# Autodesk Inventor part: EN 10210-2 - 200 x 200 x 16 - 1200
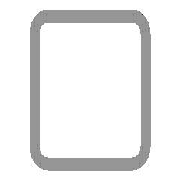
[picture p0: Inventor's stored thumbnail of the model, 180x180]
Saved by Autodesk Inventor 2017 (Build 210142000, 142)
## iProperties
IsCustomPart: 1
Created: 2016-02
Part Number: EN 10210-2 - 200 x 200 x 16 - 1200
Material: Steel, Mild
Description: Tube
Document SubType Name: Modeling
Standard: DIN
Designer: iusti
Standard Revision: 2006-07
Standards Organization: DIN
Language: en-US
Size Designation: 200 x 200 x 16
Categories: <MemberInstance><Categories><Category DisplayName="Structural Shapes" InternalName="089c4875-fa83-4c05-b084-43b9cc11f5ed" Mnemonic="GRDR"><CategoryParameter Dis
Stock Number: 200 x 200 x 16
Density: 7.85 g/cm^3
Appearance: Semi-Polished
Mass: 90285.3 g
Surface Area: 14358.6 cm^2
Volume: 11501.3 cm^3
_CCFamilyMember: 94
_CCFamilyDisplayName: DIN EN 10210-2 (Square) - Tube — Sizes in parentheses have been withdrawn
_FrameMemberDoc: Frame Member File
_Version: 15.0.0
_GetPNFromCC: 1
G_L: 1200.000 mm
G_W: 200.000 mm
G_H: 200.000 mm
+D0655DDE-97F9-4B99-A490-E36C02108510+CUTDETAIL1: Miter 45.00 deg
+B95BDB02-C4C2-4ECB-9363-19BA39C44CCB+CUTDETAIL2: Miter 45.00 deg
Author: iusti
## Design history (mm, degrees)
node "Start plane"
node "End plane"
sketch "Sketch"
  geometry: L1 (-100, -76)-(-100, 76); L2 (-76, 100)-(76, 100); L3 (100, 76)-(100, -76); L4 (76, -100)-(-76, -100); L5 (-68, 84)-(68, 84); L6 (84, 68)-(84, -68); L7 (68, -84)-(-68, -84); L8 (-84, -68)-(-84, 68); L9 (0, 146.959)-(0, -146.959) reference; L10 (-146.959, 0)-(146.959, 0) reference; A1 r 24 centre (-76, -76) between (-100, -76) and (-76, -100); A2 r 24 centre (-76, 76) between (-76, 100) and (-100, 76); A3 r 24 centre (76, 76) between (100, 76) and (76, 100); A4 r 24 centre (76, -76) between (76, -100) and (100, -76); A5 r 16 centre (-68, -68) between (-84, -68) and (-68, -84); A6 r 16 centre (-68, 68) between (-68, 84) and (-84, 68); A7 r 16 centre (68, 68) between (84, 68) and (68, 84); A8 r 16 centre (68, -68) between (68, -84) and (84, -68)
  constraints: 16 end point, 16 point on circle, 16 tangent, 8 centre point, 6 equal radius, 4 parallel, 2 perpendicular, 2 other
  dimensions: "d7" = 24 radius of A1 (= G_IR); "d10" = 200 distance between parallel lines of L2 L4 (= G_H); "d11" = 200 distance between parallel lines of L1 L3 (= G_W); "d12" = 16 distance between parallel lines of L3 L6 (= G_T); "d15" = 100 distance between parallel lines of L2 L10 (= 0.5 x d10); "d16" = 100 distance between parallel lines of L9 L3 (= 0.5 x d11); "d19" = 16 radius of A5 (= G_T); "d20" = 16 distance between parallel lines of L4 L7 (= G_T)
extrude "Body" new body sketch "Sketch" stored distance "d3" = 1200 (= G_L); taper "d4" = 0 deg
node "Driven Length"
  sketch "Sketch3"
    geometry: L1 (0, 0)-(10, 0) reference
    constraints: 2 end point, 1 horizontal
  workplane "Work Plane3"
  sketch "Sketch4"
    geometry: L1 (-2, -100)-(12, -100) reference; L2 (-2, 1100)-(12, 1100) reference
    dimensions: "d18" = 1200 distance between parallel lines of L1 L2 (derived)
workplane "Work Plane4"
split "Split1"
workplane "Work Plane5"
split "Split2"
body "Solid1"
other parameters: "G_W" = 200 [user parameter; used in 1 equation term], "G_H" = 200 [user parameter; used in 1 equation term], "G_T" = 16 [user parameter; used in 3 equation terms], "G_IR" = 24 [user parameter; used in 1 equation term], "G_L" = 1200 (= d18) [user parameter; used in 1 equation term], "d17" = 90 deg
